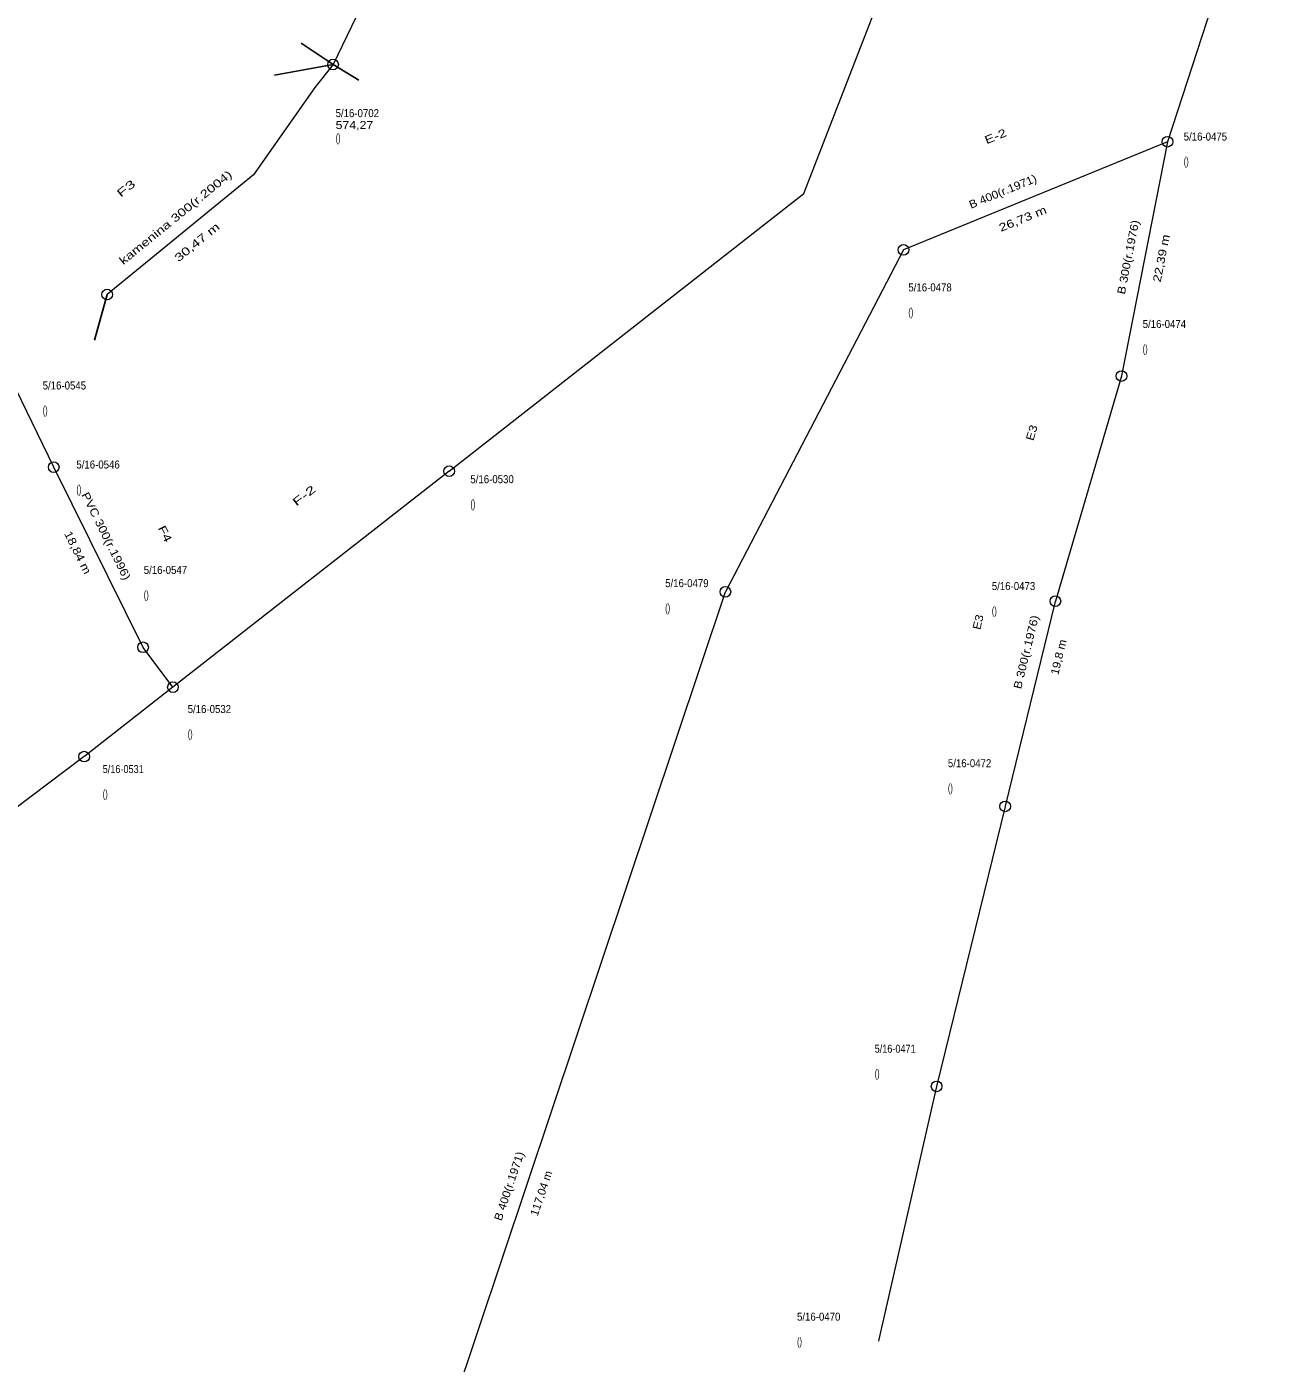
# Model space of a CAD drawing. Extents: x -710854 to -709799, y -1117012 to -1115891.
# Drawn here: x -710621.7 to -710504.7, y -1116848.7 to -1116723.5 of the extents above; entities that cross this region are included whole.
import ezdxf
from ezdxf.enums import TextEntityAlignment as Align

# ---------------------------------------------------------------- set-up
doc = ezdxf.new("R2010")
doc.units = 0
doc.header["$LTSCALE"] = 0.3
for name, color, linetype, lineweight in [('35', 7, 'Continuous', 25), ('38', 7, 'Continuous', 13), ('44', 7, 'Continuous', 13)]:
    doc.layers.add(name, color=color, linetype=linetype, lineweight=lineweight)
doc.layers.add('48', color=7, linetype='Continuous')

msp = doc.modelspace()

# ---------------------------------------------------------------- linework, layer by layer
at = {"layer": '35'}
for p, q in [((-710593.031, -1116727.011), (-710596.01, -1116725)), ((-710593.031, -1116727.011), (-710598.53, -1116728.01)), ((-710593.031, -1116727.011), (-710590.63, -1116728.47)), ((-710614.2, -1116748.562), (-710615.39, -1116752.85))]:
    msp.add_line(p, q, dxfattribs=at)
at = {"layer": '38'}
for p, q in [((-710619.203, -1116764.754), (-710623.76, -1116755.36)), ((-710582.15, -1116765.12), (-710608.03, -1116785.37)), ((-710530.054, -1116796.545), (-710536.483, -1116822.794))]:
    msp.add_line(p, q, dxfattribs=at)
for points in [[(-710582.15, -1116765.12), (-710548.91, -1116739.11), (-710526.959, -1116682.488)], [(-710504.658, -1116702.963), (-710504.662, -1116702.976), (-710514.85, -1116734.24)], [(-710584.471, -1116709.24), (-710584.471, -1116709.241), (-710593.03, -1116727.01), (-710593.031, -1116727.011)], [(-710593.031, -1116727.011), (-710594.751, -1116729.151), (-710600.49, -1116737.361), (-710614.2, -1116748.562)], [(-710514.85, -1116734.24), (-710539.577, -1116744.377), (-710539.581, -1116744.385), (-710556.276, -1116776.44)], [(-710514.85, -1116734.24), (-710519.153, -1116756.176), (-710519.159, -1116756.207)], [(-710519.159, -1116756.207), (-710519.16, -1116756.21), (-710525.35, -1116777.31), (-710525.351, -1116777.312)], [(-710610.832, -1116781.636), (-710610.852, -1116781.596), (-710619.137, -1116764.887), (-710619.18, -1116764.8), (-710619.203, -1116764.754)], [(-710556.276, -1116776.44), (-710556.297, -1116776.481), (-710593.42, -1116887.43)], [(-710525.351, -1116777.312), (-710525.359, -1116777.348), (-710530.05, -1116796.53), (-710530.051, -1116796.536), (-710530.054, -1116796.545)], [(-710608.03, -1116785.37), (-710610.83, -1116781.64), (-710610.832, -1116781.636)], [(-710608.03, -1116785.37), (-710616.303, -1116791.841), (-710616.34, -1116791.87), (-710616.356, -1116791.882)], [(-710616.356, -1116791.882), (-710710.081, -1116862.611), (-710710.107, -1116862.63)], [(-710536.483, -1116822.794), (-710536.487, -1116822.81), (-710541.921, -1116846.641), (-710541.93, -1116846.68), (-710541.931, -1116846.686)]]:
    msp.add_lwpolyline(points, dxfattribs=at)
at = {"layer": '44'}
for centre in [(-710593.031, -1116727.011), (-710514.85, -1116734.24), (-710539.581, -1116744.385), (-710614.2, -1116748.562), (-710519.159, -1116756.207), (-710619.203, -1116764.754), (-710582.15, -1116765.12), (-710556.276, -1116776.44), (-710525.351, -1116777.312), (-710610.832, -1116781.636), (-710608.03, -1116785.37), (-710616.356, -1116791.882), (-710530.054, -1116796.545), (-710536.483, -1116822.794)]:
    msp.add_circle(centre, 0.5, dxfattribs=at)

# ---------------------------------------------------------------- texts
at = {"layer": '48'}
for s, width, p in [('5/16-0702', 0.9, (-710592.791, -1116731.942)), ('574,27 ', 1.15, (-710592.791, -1116733.052)), ('()', 0.7, (-710592.791, -1116734.252)), ('5/16-0475', 0.9, (-710513.329, -1116734.138)), ('()', 0.7, (-710513.329, -1116736.448)), ('5/16-0478', 0.9, (-710539.13, -1116748.274)), ('()', 0.7, (-710539.13, -1116750.584)), ('5/16-0474', 0.9, (-710517.172, -1116751.704)), ('()', 0.7, (-710517.172, -1116754.015)), ('5/16-0545', 0.9, (-710620.238, -1116757.469)), ('()', 0.7, (-710620.238, -1116759.779)), ('5/16-0546', 0.9, (-710617.082, -1116764.879)), ('5/16-0530', 0.9, (-710580.164, -1116766.252)), ('()', 0.7, (-710617.082, -1116767.19)), ('()', 0.7, (-710580.164, -1116768.562)), ('5/16-0547', 0.9, (-710610.769, -1116774.761)), ('5/16-0479', 0.9, (-710561.912, -1116775.996)), ('5/16-0473', 0.9, (-710531.307, -1116776.27)), ('()', 0.7, (-710610.769, -1116777.071)), ('()', 0.7, (-710561.912, -1116778.306)), ('()', 0.7, (-710531.307, -1116778.58)), ('5/16-0532', 0.9, (-710606.652, -1116787.799)), ('()', 0.7, (-710606.652, -1116790.109)), ('5/16-0472', 0.9, (-710535.424, -1116792.876)), ('5/16-0531', 0.85, (-710614.612, -1116793.425)), ('()', 0.7, (-710535.424, -1116795.186)), ('()', 0.7, (-710614.612, -1116795.735)), ('5/16-0471', 0.85, (-710542.286, -1116819.638)), ('()', 0.7, (-710542.286, -1116821.948)), ('5/16-0470', 0.9, (-710549.56, -1116844.753)), ('()', 0.7, (-710549.56, -1116847.063))]:
    msp.add_text(s, height=0.75, dxfattribs=dict(at, width=width)).set_placement(p)
for s, rotation, width, p in [('E-2', 22.29, 1.35, (-710530.8227, -1116734.0874)), ('kamenina 300(r.2004)', 39.25, 1.35, (-710607.5518, -1116741.6325)), ('F3', 39.25, 1.6, (-710612.1923, -1116738.9157)), ('B 400(r.1971)', 22.29, 1.1, (-710530.1377, -1116739.2535)), ('B 400(r.1971)', 22.29, 1.1, (-710530.1377, -1116739.2535)), ('26,73 m', 22.29, 1.3, (-710528.2717, -1116741.8059)), ('26,73 m', 22.29, 1.3, (-710528.2717, -1116741.8059)), ('30,47 m', 39.25, 1.4, (-710605.5403, -1116743.9531)), ('B 300(r.1976)', 78.9, 1.15, (-710518.1698, -1116745.1347)), ('22,39 m', 78.9, 1.25, (-710515.0615, -1116745.2402)), ('E3', 73.65, 1.2, (-710527.2101, -1116761.6251)), ('PVC 300(r.1996)', 296.37, 1.2, (-710614.6262, -1116771.3729)), ('F-2', 38.04, 1.6, (-710595.5241, -1116767.7113)), ('18,84 m', 296.37, 1.2, (-710617.2859, -1116772.9194)), ('F4', 296.37, 1.35, (-710609.1056, -1116771.1629)), ('E3', 76.26, 1.15, (-710532.2344, -1116779.3606)), ('B 300(r.1976)', 76.26, 1.15, (-710527.7328, -1116782.1686)), ('19,8 m', 76.26, 1.1, (-710524.6879, -1116782.6401)), ('B 400(r.1971)', 71.5, 1.1, (-710576.1833, -1116832.257)), ('117,04 m', 71.5, 1.05, (-710573.1696, -1116832.931))]:
    msp.add_text(s, height=0.75, rotation=rotation, dxfattribs=dict(at, width=width)).set_placement(p, align=Align.CENTER)

doc.saveas('drawing.dxf')
